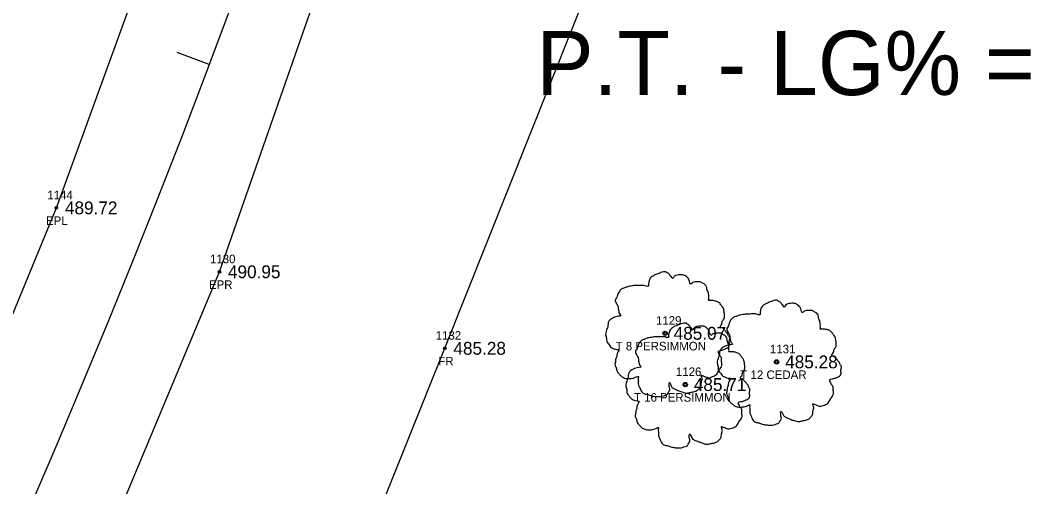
# Model space of a CAD drawing. Extents: x 1649047 to 1650429, y 896228 to 898747.
# Drawn here: x 1649848.7 to 1649966.7, y 897339.2 to 897393.8 of the extents above; entities that cross this region are included whole.
import ezdxf

# ---------------------------------------------------------------- set-up
doc = ezdxf.new("R2010")
doc.units = 0
for name, color, linetype in [('RD_EX_Fence_Other', 7, 'Continuous'), ('RD_EX_Fence_Other_txCode', 7, 'Continuous'), ('RD_EX_Road', 7, 'Continuous'), ('RD_EX_Road_txCode', 7, 'Continuous'), ('RD_EX_TX_Fence_Other_ELEV', 7, 'Continuous'), ('RD_EX_TX_Road_ELEV', 7, 'Continuous'), ('RD_EX_TX_VEG_ELEV', 7, 'Continuous'), ('RD_EX_VEG', 7, 'Continuous'), ('RD_EX_VEG_txCode', 7, 'Continuous'), ('RD_HC_Cl', 7, 'Continuous'), ('RD_HC_Data', 7, 'Continuous'), ('RD_HC_Data_Tic', 7, 'Continuous'), ('RD_SMD_Locator', 7, 'Continuous')]:
    doc.layers.add(name, color=color, linetype=linetype)

msp = doc.modelspace()

# ---------------------------------------------------------------- linework, layer by layer
at = {"layer": 'RD_EX_Fence_Other'}
msp.add_lwpolyline([(1649933.62, 897283.21), (1649871.55, 897272.45), (1649870.07, 897285.06), (1649898.31, 897355.41), (1649920.55, 897411.26), (1649908.3, 897415.25)], dxfattribs=at)
at = {"layer": 'RD_EX_Road'}
for points in [[(1649459.38, 896805.71), (1649486.55, 896839.62), (1649513.65, 896873.34), (1649538.22, 896902.56), (1649549.43, 896916.62), (1649583.1, 896957.27), (1649614.8, 896995.02), (1649647.06, 897035.69), (1649677.62, 897074.51), (1649708.33, 897114.44), (1649735.5, 897151.61), (1649762.11, 897192.19), (1649788.21, 897235.29), (1649812.17, 897279.73), (1649834.32, 897326.54), (1649852.94, 897371.82), (1649867.51, 897411.96)], [(1649474.75, 896792.65), (1649502.78, 896827.35), (1649565.2, 896903.92), (1649598.28, 896943.71), (1649629.8, 896982.26), (1649667.92, 897029.33), (1649693.13, 897061.44), (1649723.58, 897101.84), (1649752.37, 897141.09), (1649779.72, 897182.3), (1649806.12, 897225.84), (1649830.13, 897270.79), (1649852.39, 897317.43), (1649871.98, 897364.35), (1649886.55, 897406.09)]]:
    msp.add_lwpolyline(points, dxfattribs=at)
at = {"layer": 'RD_EX_VEG'}
for centre, radius in [((1649924.03, 897357.16), 0.25), ((1649924.02, 897357.14), 0.0001), ((1649937.06, 897353.82), 0.25), ((1649937.05, 897353.81), 0.0001), ((1649926.39, 897351.17), 0.25), ((1649926.37, 897351.15), 0.0001)]:
    msp.add_circle(centre, radius, dxfattribs=at)
for points in [[(1649924.16, 897364.33), (1649923.86, 897364.35), (1649923.54, 897364.25), (1649923.29, 897364.15), (1649923.06, 897364.08), (1649922.84, 897363.98), (1649922.54, 897363.8), (1649922.31, 897363.6), (1649922.19, 897363.35), (1649922.14, 897363.13), (1649922.09, 897362.85), (1649922.09, 897362.68), (1649921.96, 897362.65), (1649921.81, 897362.68), (1649921.56, 897362.75), (1649921.31, 897362.75), (1649921.06, 897362.75), (1649920.71, 897362.73), (1649920.36, 897362.73), (1649920.09, 897362.68), (1649919.76, 897362.63), (1649919.39, 897362.5), (1649919.04, 897362.38), (1649918.74, 897362.13), (1649918.49, 897361.65), (1649918.37, 897361.3), (1649918.22, 897361.05), (1649918.37, 897360.6), (1649918.54, 897360.25), (1649918.57, 897360.05), (1649918.64, 897359.63), (1649918.74, 897359.4), (1649918.87, 897359.2), (1649918.79, 897359.18), (1649918.42, 897359.13), (1649918.12, 897359.03), (1649917.69, 897358.8), (1649917.47, 897358.58), (1649917.37, 897358.25), (1649917.34, 897357.9), (1649917.24, 897357.7), (1649917.17, 897357.43), (1649917.14, 897357.35), (1649917.09, 897357.03), (1649917.19, 897356.58), (1649917.22, 897356.23), (1649917.34, 897356.01), (1649917.49, 897355.83), (1649917.67, 897355.58), (1649918.07, 897355.36), (1649918.39, 897355.26), (1649918.59, 897355.23), (1649918.42, 897354.73), (1649918.37, 897354.38), (1649918.24, 897353.98), (1649918.24, 897353.91), (1649918.19, 897353.43), (1649918.34, 897353.11), (1649918.42, 897352.73), (1649918.59, 897352.51), (1649918.87, 897352.21), (1649919.19, 897351.98), (1649919.69, 897351.86), (1649920.09, 897351.88), (1649920.66, 897352.06), (1649920.91, 897352.13), (1649920.89, 897351.96), (1649920.91, 897351.58), (1649920.91, 897351.16), (1649921.06, 897350.83), (1649921.16, 897350.56), (1649921.31, 897350.31), (1649921.64, 897350.08), (1649922.04, 897350.01), (1649922.46, 897349.86), (1649922.91, 897349.78), (1649923.41, 897349.76), (1649924.01, 897349.91), (1649924.29, 897350.03), (1649924.39, 897350.21), (1649924.59, 897350.58), (1649924.54, 897350.81), (1649924.56, 897351.41), (1649924.66, 897351.23), (1649924.84, 897350.88), (1649925.34, 897350.58), (1649925.74, 897350.41), (1649926.21, 897350.26), (1649926.51, 897350.18), (1649926.99, 897350.26), (1649927.36, 897350.33), (1649927.74, 897350.46), (1649928.04, 897350.73), (1649928.21, 897351.01), (1649928.26, 897351.28), (1649928.34, 897351.66), (1649928.39, 897351.83)], [(1649928.39, 897351.83), (1649928.31, 897352.01), (1649928.26, 897352.26), (1649928.34, 897352.23), (1649928.51, 897352.18), (1649928.79, 897352.06), (1649929.01, 897351.98), (1649929.34, 897352.01), (1649929.61, 897352.11), (1649930.06, 897352.38), (1649930.34, 897352.86), (1649930.61, 897353.26), (1649930.68, 897353.58), (1649930.63, 897353.81), (1649930.61, 897354.31), (1649930.41, 897354.56), (1649930.36, 897354.68), (1649930.26, 897355.08), (1649930.34, 897355.13), (1649930.61, 897355.18), (1649930.98, 897355.31), (1649931.26, 897355.43), (1649931.48, 897355.61), (1649931.56, 897355.83), (1649931.53, 897356.23), (1649931.58, 897356.63), (1649931.51, 897356.78), (1649931.41, 897356.93), (1649931.33, 897357.13), (1649931.18, 897357.28), (1649931.08, 897357.43), (1649930.98, 897357.53), (1649930.86, 897357.68), (1649930.68, 897357.8), (1649930.54, 897357.85), (1649930.49, 897358), (1649930.63, 897358.2), (1649930.68, 897358.3), (1649930.71, 897358.53), (1649930.93, 897358.88), (1649930.98, 897359.28), (1649930.93, 897359.7), (1649930.88, 897359.98), (1649930.73, 897360.25), (1649930.54, 897360.5), (1649930.41, 897360.68), (1649930.24, 897360.8), (1649929.91, 897360.93), (1649929.66, 897360.98), (1649929.31, 897360.98), (1649929.11, 897361.03), (1649929.14, 897361.08), (1649929.14, 897361.23), (1649929.14, 897361.5), (1649929.06, 897361.95), (1649928.91, 897362.45), (1649928.91, 897362.48), (1649928.81, 897362.73), (1649928.59, 897362.93), (1649928.41, 897363.03), (1649928.21, 897363.15), (1649927.96, 897363.18), (1649927.66, 897363.18), (1649927.39, 897363.13), (1649927.19, 897363.03), (1649927.01, 897362.9), (1649926.94, 897363.05), (1649926.84, 897363.35), (1649926.79, 897363.5), (1649926.64, 897363.68), (1649926.41, 897363.88), (1649925.96, 897364), (1649925.34, 897363.93), (1649925.04, 897363.73), (1649924.89, 897363.55), (1649924.84, 897363.68), (1649924.64, 897363.88), (1649924.54, 897364.05), (1649924.36, 897364.18), (1649924.21, 897364.28), (1649924.11, 897364.33)], [(1649937.19, 897360.99), (1649936.89, 897361.02), (1649936.57, 897360.92), (1649936.32, 897360.82), (1649936.09, 897360.74), (1649935.87, 897360.64), (1649935.57, 897360.47), (1649935.34, 897360.27), (1649935.22, 897360.02), (1649935.17, 897359.79), (1649935.12, 897359.52), (1649935.12, 897359.34), (1649934.99, 897359.32), (1649934.84, 897359.34), (1649934.59, 897359.42), (1649934.34, 897359.42), (1649934.09, 897359.42), (1649933.74, 897359.39), (1649933.4, 897359.39), (1649933.12, 897359.34), (1649932.8, 897359.29), (1649932.42, 897359.17), (1649932.07, 897359.04), (1649931.77, 897358.79), (1649931.52, 897358.32), (1649931.4, 897357.97), (1649931.25, 897357.72), (1649931.4, 897357.27), (1649931.57, 897356.92), (1649931.6, 897356.72), (1649931.67, 897356.29), (1649931.77, 897356.07), (1649931.9, 897355.87), (1649931.82, 897355.84), (1649931.45, 897355.79), (1649931.15, 897355.69), (1649930.72, 897355.47), (1649930.5, 897355.24), (1649930.4, 897354.92), (1649930.37, 897354.57), (1649930.27, 897354.37), (1649930.2, 897354.09), (1649930.17, 897354.02), (1649930.12, 897353.69), (1649930.22, 897353.24), (1649930.25, 897352.89), (1649930.37, 897352.67), (1649930.52, 897352.49), (1649930.7, 897352.24), (1649931.1, 897352.02), (1649931.42, 897351.92), (1649931.62, 897351.9), (1649931.45, 897351.4), (1649931.4, 897351.05), (1649931.27, 897350.65), (1649931.27, 897350.57), (1649931.22, 897350.1), (1649931.37, 897349.77), (1649931.45, 897349.4), (1649931.62, 897349.17), (1649931.9, 897348.87), (1649932.22, 897348.65), (1649932.72, 897348.52), (1649933.12, 897348.55), (1649933.7, 897348.72), (1649933.94, 897348.8), (1649933.92, 897348.62), (1649933.94, 897348.25), (1649933.94, 897347.82), (1649934.09, 897347.5), (1649934.19, 897347.22), (1649934.34, 897346.97), (1649934.67, 897346.75), (1649935.07, 897346.67), (1649935.49, 897346.52), (1649935.94, 897346.45), (1649936.44, 897346.42), (1649937.04, 897346.57), (1649937.32, 897346.7), (1649937.42, 897346.87), (1649937.62, 897347.25), (1649937.57, 897347.47), (1649937.59, 897348.07), (1649937.69, 897347.9), (1649937.87, 897347.55), (1649938.37, 897347.25), (1649938.77, 897347.07), (1649939.24, 897346.92), (1649939.54, 897346.85), (1649940.02, 897346.92), (1649940.39, 897347), (1649940.77, 897347.12), (1649941.07, 897347.4), (1649941.24, 897347.67), (1649941.29, 897347.95), (1649941.37, 897348.32), (1649941.42, 897348.5)], [(1649941.42, 897348.5), (1649941.34, 897348.67), (1649941.29, 897348.92), (1649941.37, 897348.9), (1649941.54, 897348.85), (1649941.82, 897348.72), (1649942.04, 897348.65), (1649942.37, 897348.67), (1649942.64, 897348.77), (1649943.09, 897349.05), (1649943.37, 897349.52), (1649943.64, 897349.92), (1649943.72, 897350.25), (1649943.67, 897350.47), (1649943.64, 897350.97), (1649943.44, 897351.22), (1649943.39, 897351.35), (1649943.29, 897351.75), (1649943.37, 897351.8), (1649943.64, 897351.85), (1649944.02, 897351.97), (1649944.29, 897352.09), (1649944.52, 897352.27), (1649944.59, 897352.49), (1649944.57, 897352.89), (1649944.62, 897353.29), (1649944.54, 897353.44), (1649944.44, 897353.59), (1649944.37, 897353.79), (1649944.22, 897353.94), (1649944.12, 897354.09), (1649944.02, 897354.19), (1649943.89, 897354.34), (1649943.72, 897354.47), (1649943.57, 897354.52), (1649943.52, 897354.67), (1649943.67, 897354.87), (1649943.72, 897354.97), (1649943.74, 897355.19), (1649943.97, 897355.54), (1649944.02, 897355.94), (1649943.97, 897356.37), (1649943.92, 897356.64), (1649943.77, 897356.92), (1649943.57, 897357.17), (1649943.44, 897357.34), (1649943.27, 897357.47), (1649942.94, 897357.59), (1649942.69, 897357.64), (1649942.34, 897357.64), (1649942.14, 897357.69), (1649942.17, 897357.74), (1649942.17, 897357.89), (1649942.17, 897358.17), (1649942.09, 897358.62), (1649941.94, 897359.12), (1649941.94, 897359.14), (1649941.84, 897359.39), (1649941.62, 897359.59), (1649941.44, 897359.69), (1649941.24, 897359.82), (1649940.99, 897359.84), (1649940.69, 897359.84), (1649940.42, 897359.79), (1649940.22, 897359.69), (1649940.04, 897359.57), (1649939.97, 897359.72), (1649939.87, 897360.02), (1649939.82, 897360.17), (1649939.67, 897360.34), (1649939.44, 897360.54), (1649938.99, 897360.67), (1649938.37, 897360.59), (1649938.07, 897360.39), (1649937.92, 897360.22), (1649937.87, 897360.34), (1649937.67, 897360.54), (1649937.57, 897360.72), (1649937.39, 897360.84), (1649937.24, 897360.94), (1649937.14, 897360.99)], [(1649926.52, 897358.34), (1649926.22, 897358.36), (1649925.89, 897358.26), (1649925.64, 897358.16), (1649925.42, 897358.09), (1649925.19, 897357.99), (1649924.89, 897357.81), (1649924.67, 897357.61), (1649924.54, 897357.36), (1649924.49, 897357.14), (1649924.44, 897356.86), (1649924.44, 897356.69), (1649924.32, 897356.66), (1649924.17, 897356.69), (1649923.92, 897356.76), (1649923.67, 897356.76), (1649923.42, 897356.76), (1649923.07, 897356.74), (1649922.72, 897356.74), (1649922.45, 897356.69), (1649922.12, 897356.64), (1649921.75, 897356.51), (1649921.4, 897356.39), (1649921.1, 897356.14), (1649920.85, 897355.66), (1649920.72, 897355.31), (1649920.57, 897355.06), (1649920.72, 897354.61), (1649920.9, 897354.26), (1649920.92, 897354.06), (1649921, 897353.64), (1649921.1, 897353.41), (1649921.22, 897353.21), (1649921.15, 897353.19), (1649920.77, 897353.14), (1649920.47, 897353.04), (1649920.05, 897352.81), (1649919.82, 897352.59), (1649919.72, 897352.26), (1649919.7, 897351.91), (1649919.6, 897351.71), (1649919.52, 897351.44), (1649919.5, 897351.36), (1649919.45, 897351.04), (1649919.55, 897350.59), (1649919.57, 897350.24), (1649919.7, 897350.01), (1649919.85, 897349.84), (1649920.02, 897349.59), (1649920.42, 897349.36), (1649920.75, 897349.26), (1649920.95, 897349.24), (1649920.77, 897348.74), (1649920.72, 897348.39), (1649920.6, 897347.99), (1649920.6, 897347.92), (1649920.55, 897347.44), (1649920.7, 897347.12), (1649920.77, 897346.74), (1649920.95, 897346.52), (1649921.22, 897346.22), (1649921.55, 897345.99), (1649922.05, 897345.87), (1649922.45, 897345.89), (1649923.02, 897346.07), (1649923.27, 897346.14), (1649923.24, 897345.97), (1649923.27, 897345.59), (1649923.27, 897345.17), (1649923.42, 897344.84), (1649923.52, 897344.57), (1649923.67, 897344.32), (1649923.99, 897344.09), (1649924.39, 897344.02), (1649924.82, 897343.87), (1649925.27, 897343.79), (1649925.77, 897343.77), (1649926.37, 897343.92), (1649926.64, 897344.04), (1649926.74, 897344.22), (1649926.94, 897344.59), (1649926.89, 897344.82), (1649926.92, 897345.42), (1649927.02, 897345.24), (1649927.19, 897344.89), (1649927.69, 897344.59), (1649928.09, 897344.42), (1649928.57, 897344.27), (1649928.87, 897344.19), (1649929.34, 897344.27), (1649929.72, 897344.34), (1649930.09, 897344.47), (1649930.39, 897344.74), (1649930.57, 897345.02), (1649930.62, 897345.29), (1649930.69, 897345.67), (1649930.74, 897345.84)], [(1649930.74, 897345.84), (1649930.67, 897346.02), (1649930.62, 897346.27), (1649930.69, 897346.24), (1649930.87, 897346.19), (1649931.14, 897346.07), (1649931.37, 897345.99), (1649931.69, 897346.02), (1649931.97, 897346.12), (1649932.42, 897346.39), (1649932.69, 897346.87), (1649932.97, 897347.27), (1649933.04, 897347.59), (1649932.99, 897347.82), (1649932.97, 897348.32), (1649932.77, 897348.57), (1649932.72, 897348.69), (1649932.62, 897349.09), (1649932.69, 897349.14), (1649932.97, 897349.19), (1649933.34, 897349.31), (1649933.62, 897349.44), (1649933.84, 897349.61), (1649933.92, 897349.84), (1649933.89, 897350.24), (1649933.94, 897350.64), (1649933.87, 897350.79), (1649933.77, 897350.94), (1649933.69, 897351.14), (1649933.54, 897351.29), (1649933.44, 897351.44), (1649933.34, 897351.54), (1649933.22, 897351.69), (1649933.04, 897351.81), (1649932.89, 897351.86), (1649932.84, 897352.01), (1649932.99, 897352.21), (1649933.04, 897352.31), (1649933.07, 897352.54), (1649933.29, 897352.89), (1649933.34, 897353.29), (1649933.29, 897353.71), (1649933.24, 897353.99), (1649933.09, 897354.26), (1649932.89, 897354.51), (1649932.77, 897354.69), (1649932.59, 897354.81), (1649932.27, 897354.94), (1649932.02, 897354.99), (1649931.67, 897354.99), (1649931.47, 897355.04), (1649931.49, 897355.09), (1649931.49, 897355.24), (1649931.49, 897355.51), (1649931.42, 897355.96), (1649931.27, 897356.46), (1649931.27, 897356.49), (1649931.17, 897356.74), (1649930.94, 897356.94), (1649930.77, 897357.04), (1649930.57, 897357.16), (1649930.32, 897357.19), (1649930.02, 897357.19), (1649929.74, 897357.14), (1649929.54, 897357.04), (1649929.37, 897356.91), (1649929.29, 897357.06), (1649929.19, 897357.36), (1649929.14, 897357.51), (1649928.99, 897357.69), (1649928.77, 897357.89), (1649928.32, 897358.01), (1649927.69, 897357.94), (1649927.39, 897357.74), (1649927.24, 897357.56), (1649927.19, 897357.69), (1649926.99, 897357.89), (1649926.89, 897358.06), (1649926.72, 897358.19), (1649926.57, 897358.29), (1649926.47, 897358.34)]]:
    msp.add_spline(points, degree=3, dxfattribs=at)
at = {"layer": 'RD_HC_Cl'}
msp.add_arc((1648799.37, 897792.37), 1145, 320.82481, 10.99954, dxfattribs=at)
at = {"layer": 'RD_HC_Data_Tic'}
msp.add_line((1649870.8, 897388.57), (1649867.06, 897389.98), dxfattribs=at)
at = {"layer": 'RD_SMD_Locator'}
for centre in [(1649852.94, 897371.82), (1649871.98, 897364.35), (1649924.03, 897357.16), (1649898.31, 897355.41), (1649937.06, 897353.82), (1649926.39, 897351.17)]:
    msp.add_circle(centre, 0.15, dxfattribs=at)

# ---------------------------------------------------------------- texts
at = {"layer": 'RD_EX_Fence_Other_txCode'}
for s, p in [('1132', (1649897.24, 897356.41)), ('FR', (1649897.55, 897353.41))]:
    msp.add_text(s, height=1, dxfattribs=at).set_placement(p)
at = {"layer": 'RD_EX_Road_txCode'}
for s, p in [('1144', (1649851.88, 897372.82)), ('EPL', (1649851.73, 897369.82)), ('1130', (1649870.88, 897365.35)), ('EPR', (1649870.76, 897362.35))]:
    msp.add_text(s, height=1, dxfattribs=at).set_placement(p)
at = {"layer": 'RD_EX_TX_Fence_Other_ELEV'}
msp.add_text('485.28', height=1.5, dxfattribs=at).set_placement((1649899.31, 897354.66))
at = {"layer": 'RD_EX_TX_Road_ELEV'}
for s, p in [('489.72', (1649853.94, 897371.07)), ('490.95', (1649872.98, 897363.6))]:
    msp.add_text(s, height=1.5, dxfattribs=at).set_placement(p)
at = {"layer": 'RD_EX_TX_VEG_ELEV'}
for s, p in [('485.07', (1649925.03, 897356.41)), ('485.28', (1649938.06, 897353.07)), ('485.71', (1649927.39, 897350.42))]:
    msp.add_text(s, height=1.5, dxfattribs=at).set_placement(p)
at = {"layer": 'RD_EX_VEG_txCode'}
for s, p in [('1129', (1649922.97, 897358.16)), ('T 8 PERSIMMON', (1649918.26, 897355.16)), ('1131', (1649936.28, 897354.82)), ('1126', (1649925.3, 897352.17)), ('T 12 CEDAR', (1649932.83, 897351.82)), ('T 16 PERSIMMON', (1649920.4, 897349.17))]:
    msp.add_text(s, height=1, dxfattribs=at).set_placement(p)
at = {"layer": 'RD_HC_Data'}
msp.add_text('P.T. - LG% = ', height=7.5, dxfattribs=at).set_placement((1649909, 897385))

doc.saveas('drawing.dxf')
